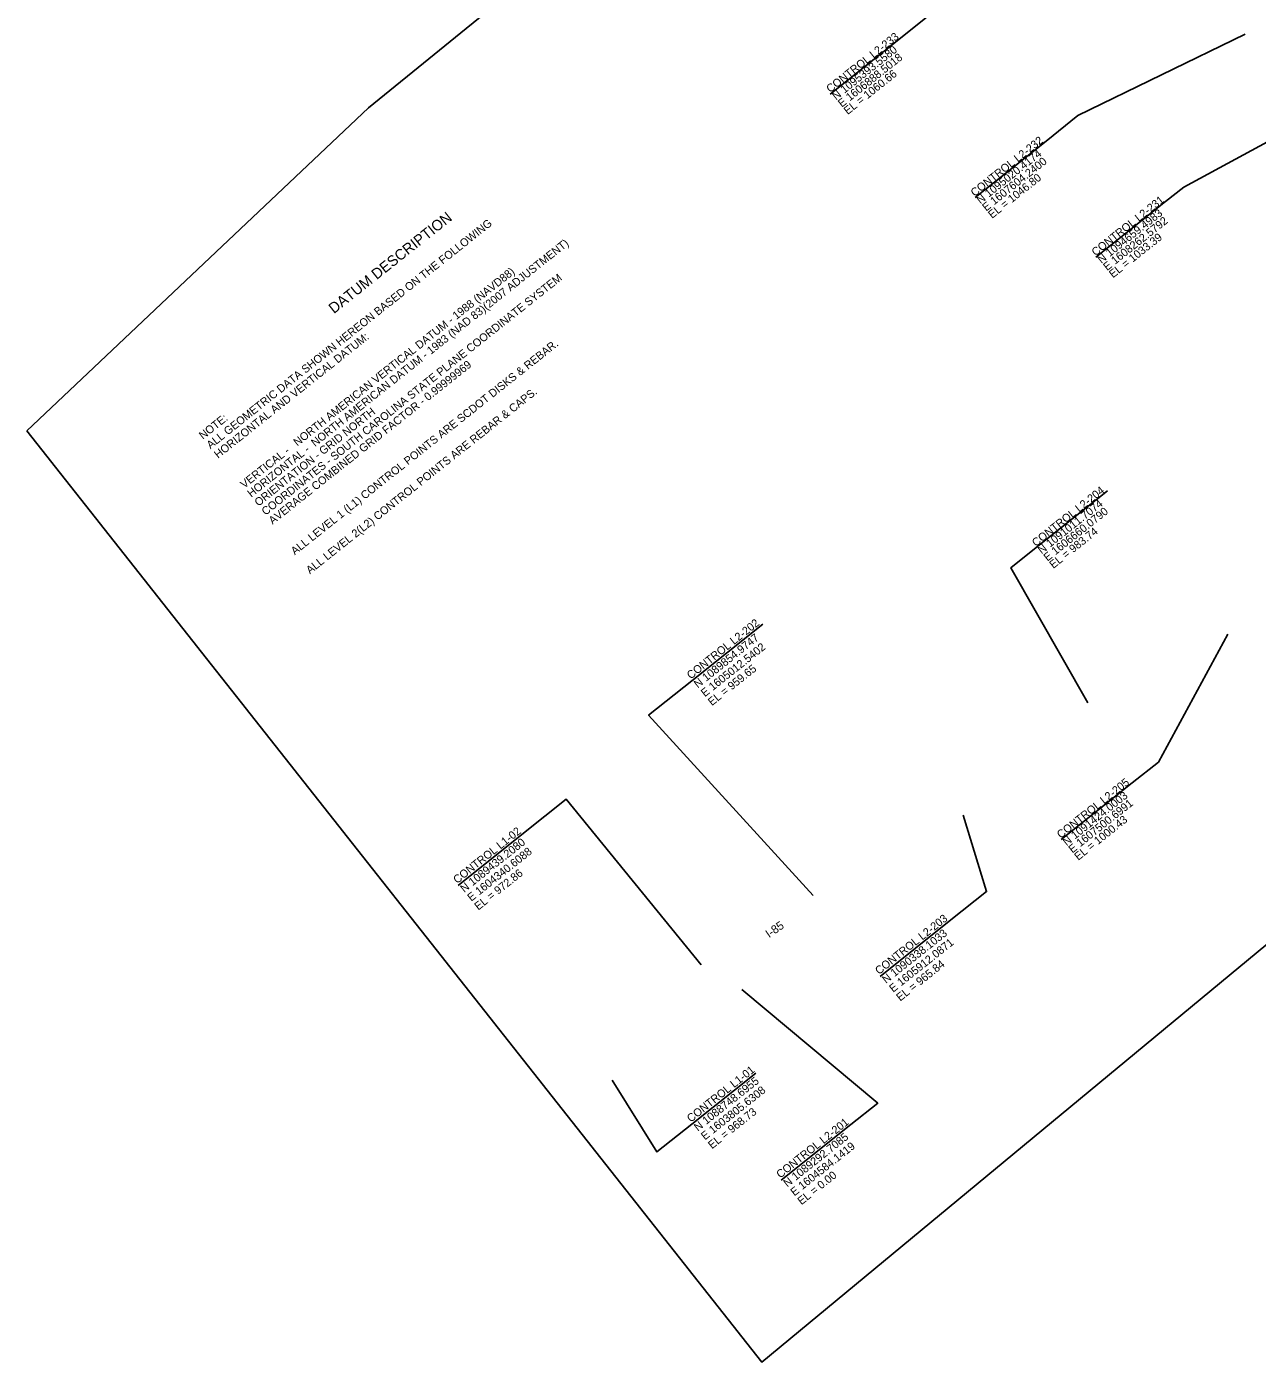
# Model space of a CAD drawing. Extents: x 1600294 to 1616097, y 1087057 to 1101809.
# Drawn here: x 1600294 to 1607677, y 1087057 to 1095066 of the extents above; entities that cross this region are included whole.
import ezdxf

# ---------------------------------------------------------------- set-up
doc = ezdxf.new("R2010")
doc.units = 0
for name, color, linetype in [('Plan_Clip', 7, 'Continuous'), ('RD_PD_GR_Tx', 7, 'Continuous'), ('RD_SHT_TX', 7, 'Continuous'), ('RD_TX_RoadID', 7, 'Continuous')]:
    doc.layers.add(name, color=color, linetype=linetype)

msp = doc.modelspace()

# ---------------------------------------------------------------- linework, layer by layer
at = {"layer": 'Plan_Clip'}
msp.add_lwpolyline([(1600293.9, 1092641.5), (1602343.7, 1094579.4), (1605167, 1096872.5), (1609119.4, 1099879.5), (1609257.5, 1099698.1), (1610590.9, 1100773.5), (1613569.3, 1097017.7), (1614735.8, 1095448.6), (1612219.9, 1092822.8), (1611099.3, 1092347), (1604705.4, 1087056.6)], close=True, dxfattribs=at)
at = {"layer": 'RD_SHT_TX'}
for p, q in [((1605546.9, 1095005.9), (1605113.4, 1094661)), ((1606409.8, 1094380.3), (1605983.4, 1094041.1)), ((1607126.6, 1094016.7), (1606709, 1093684.5)), ((1606778.2, 1092281.8), (1606351.1, 1091942)), ((1604710.5, 1091482), (1604284.1, 1091142.8)), ((1606926.9, 1090531), (1606500.5, 1090191.9)), ((1603275.1, 1090228.8), (1602882.6, 1089916.6)), ((1605839.3, 1089709.5), (1605413.7, 1089371)), ((1604668.3, 1088790.4), (1604284.6, 1088485.2)), ((1605238.9, 1088481.9), (1604821.2, 1088149.7))]:
    msp.add_line(p, q, dxfattribs=at)
for points in [[(1605546.9, 1095005.9), (1605729, 1095150.7), (1606888.5, 1095393.6)], [(1606409.8, 1094380.3), (1606601.2, 1094532.6), (1607604.2, 1095020.4)], [(1607126.6, 1094016.7), (1607235.9, 1094103.6), (1608262.6, 1094659.5)], [(1606351.1, 1091942), (1606198.1, 1091820.4), (1606660.1, 1091011.7)], [(1606926.9, 1090531), (1607083.7, 1090655.7), (1607500.7, 1091424)], [(1604284.1, 1091142.8), (1604025.2, 1090936.9), (1605012.5, 1089855)], [(1603275.1, 1090228.8), (1603531.4, 1090432.6), (1604340.6, 1089439.2)], [(1605839.3, 1089709.5), (1606053.3, 1089879.7), (1605912.1, 1090338.1)], [(1605238.9, 1088481.9), (1605400.2, 1088610.2), (1604584.1, 1089292.7)], [(1604284.6, 1088485.2), (1604074.6, 1088318.2), (1603805.6, 1088748.7)]]:
    msp.add_lwpolyline(points, dxfattribs=at)

# ---------------------------------------------------------------- texts
at = {"layer": 'RD_PD_GR_Tx'}
for s, height, rotation, p in [('ALL GEOMETRIC DATA SHOWN HEREON BASED ON THE FOLLOWING ', 48, 38.4995, (1601396.6, 1092531.3)), ('DATUM DESCRIPTION', 64, 38.4995, (1602137.1, 1093342)), ('HORIZONTAL -  NORTH AMERICAN DATUM - 1983 (NAD 83)(2007 ADJUSTMENT)', 48, 38.49354, (1601641.3, 1092240.7)), ('VERTICAL -   NORTH AMERICAN VERTICAL DATUM - 1988 (NAVD88)', 48, 38.49354, (1601599.5, 1092294.6)), ('COORDINATES - SOUTH CAROLINA STATE PLANE COORDINATE SYSTEM', 48, 38.49354, (1601726.8, 1092132.6)), ('HORIZONTAL AND VERTICAL DATUM:', 48, 38.4995, (1601442.1, 1092474.2)), ('ALL LEVEL 1 (L1) CONTROL POINTS ARE SCDOT DISKS & REBAR.', 48, 38.4995, (1601902.5, 1091895.3)), ('AVERAGE COMBINED GRID FACTOR - 0.99999969', 48, 38.49354, (1601769.4, 1092078.4)), ('ALL LEVEL 2(L2) CONTROL POINTS ARE REBAR & CAPS. ', 48, 38.4995, (1601993.4, 1091781)), ('ORIENTATION - GRID NORTH', 48, 38.49354, (1601684.2, 1092186.9)), ('NOTE:', 48, 38.4995, (1601351.2, 1092588.4))]:
    msp.add_text(s, height=height, rotation=rotation, dxfattribs=at).set_placement(p)
at = {"layer": 'RD_SHT_TX'}
for s, p in [('CONTROL L2-233', (1605114.9, 1094667.3)), ('N 1095393.5580', (1605149.7, 1094623.5)), ('E 1606888.5018', (1605184.6, 1094579.7)), ('EL = 1060.66', (1605219.4, 1094535.8)), ('CONTROL L2-232', (1605980.9, 1094044.3)), ('N 1095020.4174', (1606015.8, 1094000.4)), ('E 1607604.2400', (1606050.6, 1093956.6)), ('EL = 1046.80', (1606085.5, 1093912.8)), ('CONTROL L2-231', (1606706.5, 1093687.7)), ('N 1094659.4983', (1606741.3, 1093643.8)), ('E 1608262.5792', (1606776.2, 1093600)), ('EL = 1033.39', (1606811.1, 1093556.2)), ('CONTROL L2-204', (1606348.6, 1091945.2)), ('N 1091011.7074', (1606383.4, 1091901.3)), ('E 1606660.0790', (1606418.3, 1091857.5)), ('EL = 983.74', (1606453.2, 1091813.7)), ('CONTROL L2-202', (1604277.9, 1091150.6)), ('N 1089854.9747', (1604320.2, 1091097.4)), ('E 1605012.5402', (1604362.5, 1091044.2)), ('EL = 959.65', (1604404.8, 1090991)), ('CONTROL L2-205', (1606498, 1090195)), ('N 1091424.0003', (1606532.9, 1090151.2)), ('E 1607500.6991', (1606567.7, 1090107.4)), ('EL = 1000.43', (1606602.6, 1090063.5)), ('CONTROL L1-02', (1602876.4, 1089924.4)), ('N 1089439.2080', (1602918.7, 1089871.2)), ('E 1604340.6088', (1602961.1, 1089818)), ('EL = 972.86', (1603003.4, 1089764.8)), ('CONTROL L2-203', (1605407.5, 1089378.8)), ('N 1090338.1033', (1605449.8, 1089325.6)), ('E 1605912.0871', (1605492.1, 1089272.4)), ('EL = 965.84', (1605534.4, 1089219.2)), ('CONTROL L1-01', (1604278.4, 1088493)), ('N 1088748.6955', (1604320.7, 1088439.8)), ('E 1603805.6308', (1604363, 1088386.6)), ('EL = 968.73', (1604405.3, 1088333.4)), ('CONTROL L2-201', (1604815, 1088157.5)), ('N 1089292.7085', (1604857.3, 1088104.3)), ('E 1604584.1419', (1604899.7, 1088051.1)), ('EL = 0.00', (1604942, 1087997.8))]:
    msp.add_text(s, height=48, rotation=38.4995, dxfattribs=at).set_placement(p)
at = {"layer": 'RD_TX_RoadID'}
msp.add_text('I-85', height=50, rotation=34.44305, dxfattribs=at).set_placement((1604747.7, 1089599.4))

doc.saveas('drawing.dxf')
